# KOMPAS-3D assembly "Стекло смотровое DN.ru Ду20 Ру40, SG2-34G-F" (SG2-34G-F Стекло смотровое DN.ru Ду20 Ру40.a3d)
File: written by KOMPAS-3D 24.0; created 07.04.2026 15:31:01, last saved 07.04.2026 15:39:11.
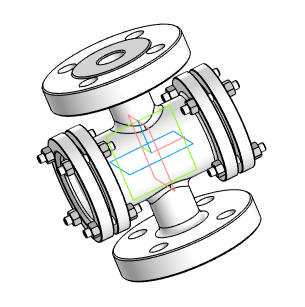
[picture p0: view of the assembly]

Document properties: Автор: Main; Полное имя файла: D:\DN.ru Аутсерс\Стекло смотровое DN.ru\Исходники\Стекло смотровое DN.ru SG2-34G-F тип В ГОСТ 21836-2021 Ду20 Ру40, углеродистая сталь, фланцевое\SG2-34G-F Стекло смотровое DN.ru Ду20 Ру40.a3d

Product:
- Component [detail]: Деталь  | qty 1  | pos. 1  | Масса: 3.673211; Автор: Main; additional columns: Типовые; source file: ДетальДеталь.m3d
- Component [detail]: Стекло  | qty 2  | pos. 2  | Масса: 0.08342; Автор: Main; source file: СтеклоСтекло.m3d
- Component [detail]: ANSI B18.2.4.2M - M6x1 - 10  | designation ANSI B18.2.4.2M - M6x1  | qty 16  | pos. 3  | Масса: 0.003008; Комментарий: Типы метрических   шестигранных гаек   2; Автор: Main; additional columns: Сталь, мягкая; source file: ANSI B18.2.4.2M - M6x1ANSI B18.2.4.2M - M6x1 - 10.m3d
- Part/product: Стекло смотровое DN.ru Ду20 Ру40  | designation SG2-34G-F
    Масса: 4.8
    Раздел спецификации: Прочие изделия
    Примечание: D500-00080

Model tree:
1. Массив по концентрической сетке:1  (labels: Грань.Твердое тело1; Ребро.Solid1; Ребро.Твердое тело1; Грань.Solid1)  (4 pattern instances)
     Шаг 2 = 360

Expressions: SG2-34G-F
Referenced files in D:\DN.ru Аутсерс\Стекло смотровое DN.ru\Исходники\Стекло смотровое DN.ru SG2-34G-F тип В ГОСТ 21836-2021 Ду20 Ру40, углеродистая сталь, фланцевое\: ДетальДеталь.m3d, СтеклоСтекло.m3d, ANSI B18.2.4.2M - M6x1ANSI B18.2.4.2M - M6x1 - 10.m3d
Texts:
  Стекло Стекло (1)
  Стекло Стекло (2)
  ANSI B18.2.4.2M - M6x1 ANSI B18.2.4.2M - M6x1 - 10 (1)
  ANSI B18.2.4.2M - M6x1 ANSI B18.2.4.2M - M6x1 - 10 (2)
  ANSI B18.2.4.2M - M6x1 ANSI B18.2.4.2M - M6x1 - 10 (3)
  ANSI B18.2.4.2M - M6x1 ANSI B18.2.4.2M - M6x1 - 10 (4)
  ANSI B18.2.4.2M - M6x1 ANSI B18.2.4.2M - M6x1 - 10 (5)
  ANSI B18.2.4.2M - M6x1 ANSI B18.2.4.2M - M6x1 - 10 (6)
  ANSI B18.2.4.2M - M6x1 ANSI B18.2.4.2M - M6x1 - 10 (7)
  ANSI B18.2.4.2M - M6x1 ANSI B18.2.4.2M - M6x1 - 10 (8)
  ANSI B18.2.4.2M - M6x1 ANSI B18.2.4.2M - M6x1 - 10 (9)
  ANSI B18.2.4.2M - M6x1 ANSI B18.2.4.2M - M6x1 - 10 (10)
  ANSI B18.2.4.2M - M6x1 ANSI B18.2.4.2M - M6x1 - 10 (11)
  ANSI B18.2.4.2M - M6x1 ANSI B18.2.4.2M - M6x1 - 10 (12)
  ANSI B18.2.4.2M - M6x1 ANSI B18.2.4.2M - M6x1 - 10 (13)
  ANSI B18.2.4.2M - M6x1 ANSI B18.2.4.2M - M6x1 - 10 (14)
  ANSI B18.2.4.2M - M6x1 ANSI B18.2.4.2M - M6x1 - 10 (15)
  ANSI B18.2.4.2M - M6x1 ANSI B18.2.4.2M - M6x1 - 10 (16)
  Ось Z.Начало координат
  Ось X.Начало координат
